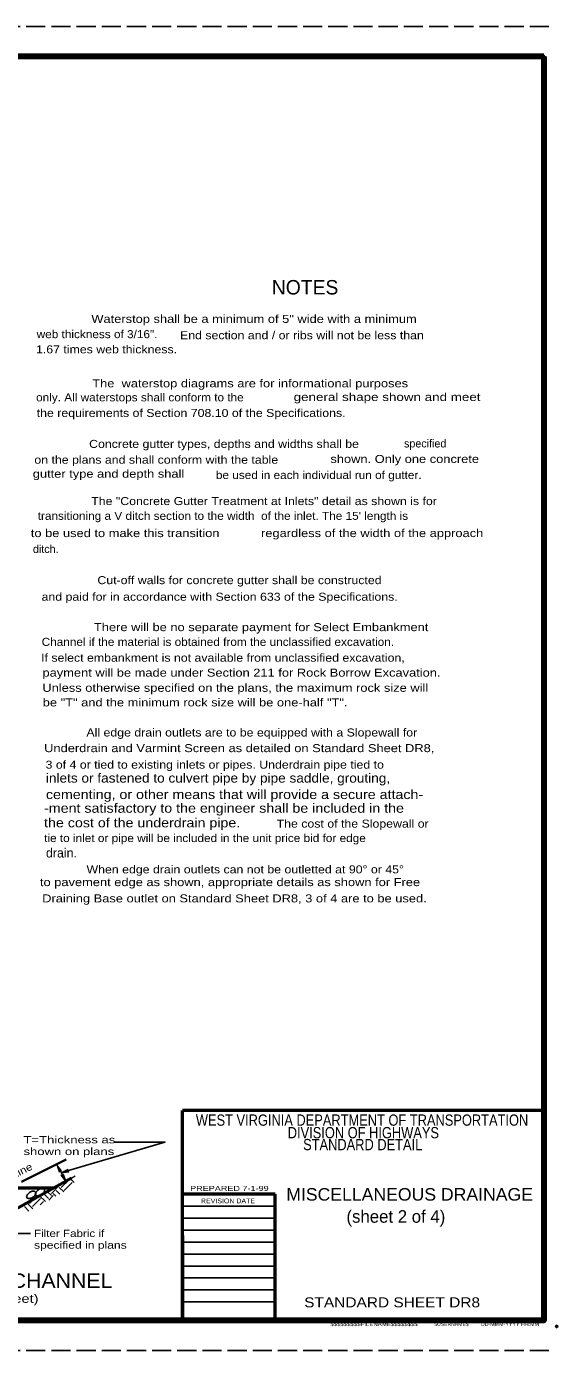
# Model space of a CAD drawing. Extents: x 72.6 to 107.3, y 36.1 to 58.1.
# Drawn here: x 98.49 to 107.3, y 36.08 to 58.08 of the extents above; entities that cross this region are included whole.
import ezdxf
from ezdxf.enums import TextEntityAlignment as Align

# ---------------------------------------------------------------- set-up
doc = ezdxf.new("R2010")
doc.units = 0
doc.header["$LTSCALE"] = 0.053
doc.header["$PDMODE"] = 32
doc.header["$PDSIZE"] = 0.0265
doc.linetypes.add('LONG_DASHED', pattern=[7.5, 6, -1.5])
for name, color, linetype, lineweight in [('1', 7, 'Continuous', 35), ('3', 7, 'Continuous', 13), ('4', 7, 'Continuous', 25), ('6', 7, 'Continuous', 13)]:
    doc.layers.add(name, color=color, linetype=linetype, lineweight=lineweight)

msp = doc.modelspace()

# ---------------------------------------------------------------- hatches: boundary and pattern name
at = {"layer": '3'}
for points in [[(99.03283, 39.0465), (99.06942, 39.06658), (98.99092, 39.16608), (98.99092, 39.16608)], [(99.06242, 38.99258), (99.099, 39.01275), (99.14092, 38.89317), (99.14092, 38.89317)], [(99.19, 39.04833), (99.17808, 39.08833), (99.06417, 39.03275), (99.06417, 39.03275)]]:
    msp.add_hatch(color=256, dxfattribs=at).paths.add_polyline_path(points)

# ---------------------------------------------------------------- linework, layer by layer
at = {"layer": '1', "linetype": 'LONG_DASHED', "lineweight": 25}
for p, q in [((107.16175, 58.07983), (72.62475, 58.07983)), ((107.16175, 36.07983), (72.62475, 36.07983))]:
    msp.add_line(p, q, dxfattribs=at)
at = {"layer": '1', "lineweight": 158}
msp.add_line((107.07842, 57.57983), (74.57842, 57.57983), dxfattribs=at)
at = {"layer": '1', "lineweight": 53}
for p, q in [((107.07842, 40.06967), (101.07842, 40.06967)), ((101.07842, 36.57983), (101.07842, 40.06967)), ((107.07842, 36.57983), (107.07842, 39.07883)), ((102.61633, 38.67883), (101.07842, 38.67883)), ((102.61633, 36.57983), (102.61633, 38.67883)), ((101.07842, 37.98983), (101.07842, 36.57983)), ((107.07842, 36.57983), (101.07842, 36.57983))]:
    msp.add_line(p, q, dxfattribs=at)
at = {"layer": '1', "lineweight": 25}
for p, q in [((98.90167, 38.6535), (98.83333, 38.72183)), ((98.90167, 38.6535), (98.83333, 38.72183)), ((98.90167, 38.68667), (99.03425, 38.81925)), ((98.90167, 38.68667), (99.03425, 38.81925)), ((99.04217, 38.67875), (98.9845, 38.73642)), ((99.04217, 38.67875), (98.9845, 38.73642)), ((99.10642, 38.71392), (99.03425, 38.78608)), ((99.10642, 38.71392), (99.03425, 38.78608)), ((99.06733, 38.81925), (99.04625, 38.84042)), ((99.06733, 38.81925), (99.04625, 38.84042)), ((99.06733, 38.78608), (99.19992, 38.91867)), ((99.06733, 38.78608), (99.19992, 38.91867)), ((99.11708, 38.869), (99.11008, 38.876)), ((99.11708, 38.869), (99.11008, 38.876)), ((99.11708, 38.73642), (99.24967, 38.869)), ((99.11708, 38.73642), (99.24967, 38.869)), ((99.28275, 38.86908), (99.2165, 38.93533)), ((99.28275, 38.86908), (99.2165, 38.93533)), ((98.59258, 38.43225), (98.50392, 38.52092)), ((98.59258, 38.43225), (98.50392, 38.52092)), ((98.53708, 38.55408), (98.53533, 38.55583)), ((98.53708, 38.55408), (98.53533, 38.55583)), ((98.53708, 38.52092), (98.61783, 38.60175)), ((98.53708, 38.52092), (98.61783, 38.60175)), ((98.58675, 38.47125), (98.71933, 38.60383)), ((98.58675, 38.47125), (98.71933, 38.60383)), ((98.80225, 38.55408), (98.70567, 38.65067)), ((98.80225, 38.55408), (98.70567, 38.65067)), ((98.80225, 38.55408), (98.70567, 38.65067)), ((98.80225, 38.55408), (98.70567, 38.65067)), ((98.7135, 38.49858), (98.76908, 38.55408)), ((98.7135, 38.49858), (98.76908, 38.55408)), ((98.85192, 38.60383), (98.7695, 38.68625)), ((98.85192, 38.60383), (98.7695, 38.68625)), ((98.86025, 38.579), (98.93475, 38.6535)), ((98.86025, 38.579), (98.93475, 38.6535)), ((98.978, 38.6435), (98.93475, 38.68667)), ((98.978, 38.6435), (98.93475, 38.68667)), ((98.52833, 38.39708), (98.45417, 38.47125)), ((98.52833, 38.39708), (98.45417, 38.47125)), ((102.61633, 38.47883), (101.07842, 38.47883)), ((102.61633, 38.27983), (101.07842, 38.27983)), ((102.61633, 38.08083), (101.07842, 38.08083)), ((102.61633, 37.88183), (101.07842, 37.88183)), ((102.61633, 37.68283), (101.07842, 37.68283)), ((102.61633, 37.48383), (101.07842, 37.48383)), ((102.61633, 37.28483), (101.07842, 37.28483)), ((102.61633, 37.08583), (101.07842, 37.08583)), ((102.61633, 36.88683), (101.07842, 36.88683))]:
    msp.add_line(p, q, dxfattribs=at)
at = {"layer": '1', "lineweight": 158}
msp.add_lwpolyline([(107.07842, 57.57983), (107.07842, 36.57983), (74.57842, 36.57983)], dxfattribs=at)
at = {"layer": '1', "lineweight": 53}
for points in [[(94.3185, 38.997), (96.51967, 37.97967), (97.50133, 37.97967), (99.23892, 38.94783)], [(94.3185, 38.997), (96.51967, 37.97967), (97.50133, 37.97967), (99.23892, 38.94783)], [(98.934, 38.77792), (98.19075, 38.77792), (97.43333, 38.41042), (96.39892, 38.41042), (95.47858, 38.84625), (94.64467, 38.84625)]]:
    msp.add_lwpolyline(points, dxfattribs=at)
at = {"layer": '1'}
for p in [(107.07842, 57.57983), (107.07842, 36.57983), (107.29142, 36.47983)]:
    msp.add_point(p, dxfattribs=at)
at = {"layer": '3', "lineweight": 35}
msp.add_line((98.40742, 38.88533), (99.14867, 39.25283), dxfattribs=at)
at = {"layer": '3'}
for p, q in [((99.05108, 39.05658), (99.08075, 39.00275)), ((99.19508, 38.923), (99.29867, 38.97992))]:
    msp.add_line(p, q, dxfattribs=at)
at = {"layer": '3', "lineweight": 25}
for points in [[(99.184, 39.06833), (100.78742, 39.54383), (99.94275, 39.54383)], [(98.07333, 38.15683), (98.17433, 38.02592), (98.55717, 38.02592)]]:
    msp.add_lwpolyline(points, dxfattribs=at)
at = {"layer": '3'}
for points in [[(99.03283, 39.0465), (99.06942, 39.06658), (98.99092, 39.16608), (98.99092, 39.16608)], [(99.06242, 38.99258), (99.099, 39.01275), (99.14092, 38.89317), (99.14092, 38.89317)], [(99.19, 39.04833), (99.17808, 39.08833), (99.06417, 39.03275), (99.06417, 39.03275)]]:
    msp.add_lwpolyline(points, close=True, dxfattribs=at)
at = {"layer": '4'}
for centre, radius, start, end in [((98.62188, 38.5826), 0.14793, 109.47631, 122.81482), ((98.60505, 38.63023), 0.09739, 93.02881, 109.47763), ((98.60317, 38.66571), 0.06186, 68.73244, 93.05444), ((98.61512, 38.69646), 0.02887, 32.82904, 68.71961), ((98.73024, 38.66083), 0.09735, 136.15944, 152.60826), ((98.76671, 38.62572), 0.14796, 122.79611, 136.13461), ((98.76671, 38.62577), 0.14793, 109.47631, 122.81482), ((98.74988, 38.6734), 0.09739, 93.02881, 109.47763), ((98.74801, 38.70888), 0.06186, 68.73244, 93.05444), ((98.75996, 38.73963), 0.02887, 32.82904, 68.71961), ((98.7271, 38.74136), 0.06181, 332.60197, 356.92397), ((98.75991, 38.73958), 0.02897, 356.96675, 32.85731), ((98.52095, 38.63567), 0.02888, 176.85974, 212.7503), ((98.55395, 38.63398), 0.06191, 152.62903, 176.95103), ((98.52095, 38.63576), 0.02893, 212.92432, 248.81488), ((98.58541, 38.61767), 0.09735, 136.15944, 152.60826), ((98.53305, 38.66642), 0.06188, 248.63072, 272.95272), ((98.62188, 38.58256), 0.14796, 122.79611, 136.13461), ((98.53108, 38.7019), 0.09739, 273.02881, 289.47763), ((98.51425, 38.74953), 0.14793, 289.47631, 302.81482), ((98.51425, 38.74939), 0.1478, 302.84584, 316.18434), ((98.55053, 38.71465), 0.09757, 316.13726, 332.58607), ((98.66579, 38.67883), 0.02888, 176.85974, 212.7503), ((98.69879, 38.67715), 0.06191, 152.62903, 176.95103), ((98.58227, 38.6982), 0.06181, 332.60197, 356.92397), ((98.61508, 38.69642), 0.02897, 356.96675, 32.85731), ((98.66579, 38.67893), 0.02893, 212.92432, 248.81488), ((98.67788, 38.70958), 0.06188, 248.63072, 272.95272), ((98.67591, 38.74507), 0.09739, 273.02881, 289.47763), ((98.65908, 38.79269), 0.14793, 289.47631, 302.81482), ((98.65908, 38.79255), 0.1478, 302.84584, 316.18434), ((98.69536, 38.75782), 0.09757, 316.13726, 332.58607)]:
    msp.add_arc(centre, radius, start, end, dxfattribs=at)
at = {"layer": '6'}
for p, q in [((98.99033, 39.16575), (98.99042, 39.16575)), ((99.14033, 38.89283), (99.14042, 38.89283)), ((99.14092, 38.89317), (99.141, 38.89317))]:
    msp.add_line(p, q, dxfattribs=at)

# ---------------------------------------------------------------- texts
at = {"layer": '1'}
for s, height, width, p in [('The "Concrete Gutter Treatment at Inlets" detail as shown is for', 0.133, 1.15, (99.56433, 50.12742)), ("transitioning a V ditch section to the width  of the inlet. The 15' length is", 0.133, 1.1, (98.67558, 49.88217)), ('to be used to make this transition ', 0.133, 1.2, (98.561, 49.5955)), ('regardless of the width of the approach ', 0.133, 1.2, (102.38292, 49.59567)), ('Cut-off walls for concrete gutter shall be constructed ', 0.133, 1.15, (99.66642, 48.8135)), ('and paid for in accordance with Section 633 of the Specifications.', 0.133, 1.15, (98.73967, 48.53792)), ('All edge drain outlets are to be equipped with a Slopewall for', 0.133, 1.15, (99.48358, 46.28225)), ('Underdrain and Varmint Screen as detailed on Standard Sheet DR8,', 0.133, 1.2, (98.78275, 46.0225)), ('3 of 4 or tied to existing inlets or pipes. Underdrain pipe tied to ', 0.133, 1.15, (98.80592, 45.74825)), ('inlets or fastened to culvert pipe by pipe saddle, grouting,', 0.1536, 1.1, (98.8115, 45.51583)), ('cementing, or other means that will provide a secure attach-', 0.1536, 1.15, (98.8115, 45.24283)), ('-ment satisfactory to the engineer shall be included in the', 0.1536, 1.15, (98.78125, 45.01533)), ('the cost of the underdrain pipe.', 0.1536, 1.15, (98.78117, 44.77267)), ('The cost of the Slopewall or', 0.133, 1.15, (102.642, 44.76825)), ('tie to inlet or pipe will be included in the unit price bid for edge ', 0.133, 1.1, (98.78275, 44.52833)), ('When edge drain outlets can not be outletted at 90° or 45°', 0.133, 1.15, (99.486, 44.00775)), ('to pavement edge as shown, appropriate details as shown for Free', 0.133, 1.2, (98.7125, 43.79617)), ('Draining Base outlet on Standard Sheet DR8, 3 of 4 are to be used.', 0.133, 1.2, (98.75025, 43.52583)), ('REVISION DATE', 0.079, 1.1, (101.3855, 38.52617)), ('$$$$$$$$$FILENAME$$$$$$$$', 0.06, 1.25, (103.53417, 36.48808)), ('$USERNAME$', 0.06, 1.05, (105.25825, 36.48808)), ('DD-MMM-YYYY HH:MM', 0.06, 1.1, (106.03183, 36.48808))]:
    msp.add_text(s, height=height, dxfattribs=dict(at, width=width)).set_placement(p)
msp.add_text('drain.', height=0.1536, dxfattribs=at).set_placement((98.81283, 44.27217))
for s, height, width, p in [('WEST VIRGINIA DEPARTMENT OF TRANSPORTATION', 0.1875, 0.85, (104.06017, 39.81475)), ('DIVISION OF HIGHWAYS', 0.1875, 0.85, (104.08204, 39.60583)), ('STANDARD DETAIL', 0.1875, 0.85, (104.07075, 39.40767)), (' PREPARED 7-1-99 ', 0.08333, 1.35, (101.85742, 38.73158)), (' MISCELLANEOUS DRAINAGE ', 0.2083, 1.05, (104.84967, 38.57033)), ('STANDARD SHEET DR8       ', 0.1667, 1.15, (104.80854, 36.79692))]:
    msp.add_text(s, height=height, dxfattribs=dict(at, width=width)).set_placement(p, align=Align.CENTER)
msp.add_text('     (sheet 2 of 4)     ', height=0.2083, dxfattribs=at).set_placement((104.62162, 38.20317), align=Align.CENTER)
at = {"layer": '3'}
for s, height, p in [('NOTES', 0.24, (102.5615, 53.62675)), ('specified', 0.133, (104.75717, 51.08492)), ('ditch.', 0.133, (98.59658, 49.33133))]:
    msp.add_text(s, height=height, dxfattribs=at).set_placement(p)
for s, height, width, p in [('Waterstop shall be a minimum of 5" wide with a minimum', 0.133, 1.2, (99.56633, 53.15433)), ('web thickness of 3/16".', 0.133, 1.1, (98.658, 52.90092)), ('End section and / or ribs will not be less than ', 0.133, 1.15, (101.03808, 52.883)), ('1.67 times web thickness.', 0.133, 1.15, (98.64725, 52.64858)), ('The  waterstop diagrams are for informational purposes', 0.133, 1.2, (99.58117, 52.08417)), ('only. All waterstops shall conform to the', 0.133, 1.1, (98.64875, 51.85108)), ('general shape shown and meet ', 0.133, 1.25, (102.92467, 51.85708)), ('the requirements of Section 708.10 of the Specifications.', 0.133, 1.15, (98.65867, 51.59167)), ('Concrete gutter types, depths and widths shall be', 0.133, 1.15, (99.52908, 51.07733)), ('on the plans and shall conform with the table', 0.133, 1.15, (98.61975, 50.81475)), ('shown. Only one concrete ', 0.133, 1.2, (103.53458, 50.82742)), (' gutter type and depth shall', 0.133, 1.2, (98.534, 50.58225)), ('be used in each individual run of gutter.', 0.133, 1.1, (101.63392, 50.56075)), ('There will be no separate payment for Select Embankment', 0.133, 1.2, (99.60883, 48.03275)), ('Channel if the material is obtained from the unclassified excavation.', 0.133, 1.1, (98.74108, 47.788)), ('If select embankment is not available from unclassified excavation,', 0.133, 1.15, (98.73217, 47.52492)), ('payment will be made under Section 211 for Rock Borrow Excavation.', 0.133, 1.2, (98.75483, 47.27692)), ('Unless otherwise specified on the plans, the maximum rock size will', 0.133, 1.2, (98.75308, 47.025)), ('be "T" and the minimum rock size will be one-half "T".', 0.133, 1.2, (98.759, 46.78225)), ('T=Thickness as', 0.12, 1.35, (98.44017, 39.5215)), ('shown on plans', 0.12, 1.35, (98.44017, 39.32725)), ('Filter Fabric if', 0.12, 1.2, (98.61417, 37.96608)), ('specified in plans', 0.12, 1.25, (98.61417, 37.77175)), ('SELECT EMBANKMENT CHANNEL', 0.24, 1.1, (94.16717, 37.12008)), ('(For Widths Exceeding 8 Feet)', 0.14, 1.3, (95.38892, 36.87225))]:
    msp.add_text(s, height=height, dxfattribs=dict(at, width=width)).set_placement(p)
at = {"layer": '3', "width": 1.2}
msp.add_text('Flow Line', height=0.12, rotation=26.88, dxfattribs=at).set_placement((97.86775, 38.7235))

doc.saveas('drawing.dxf')
